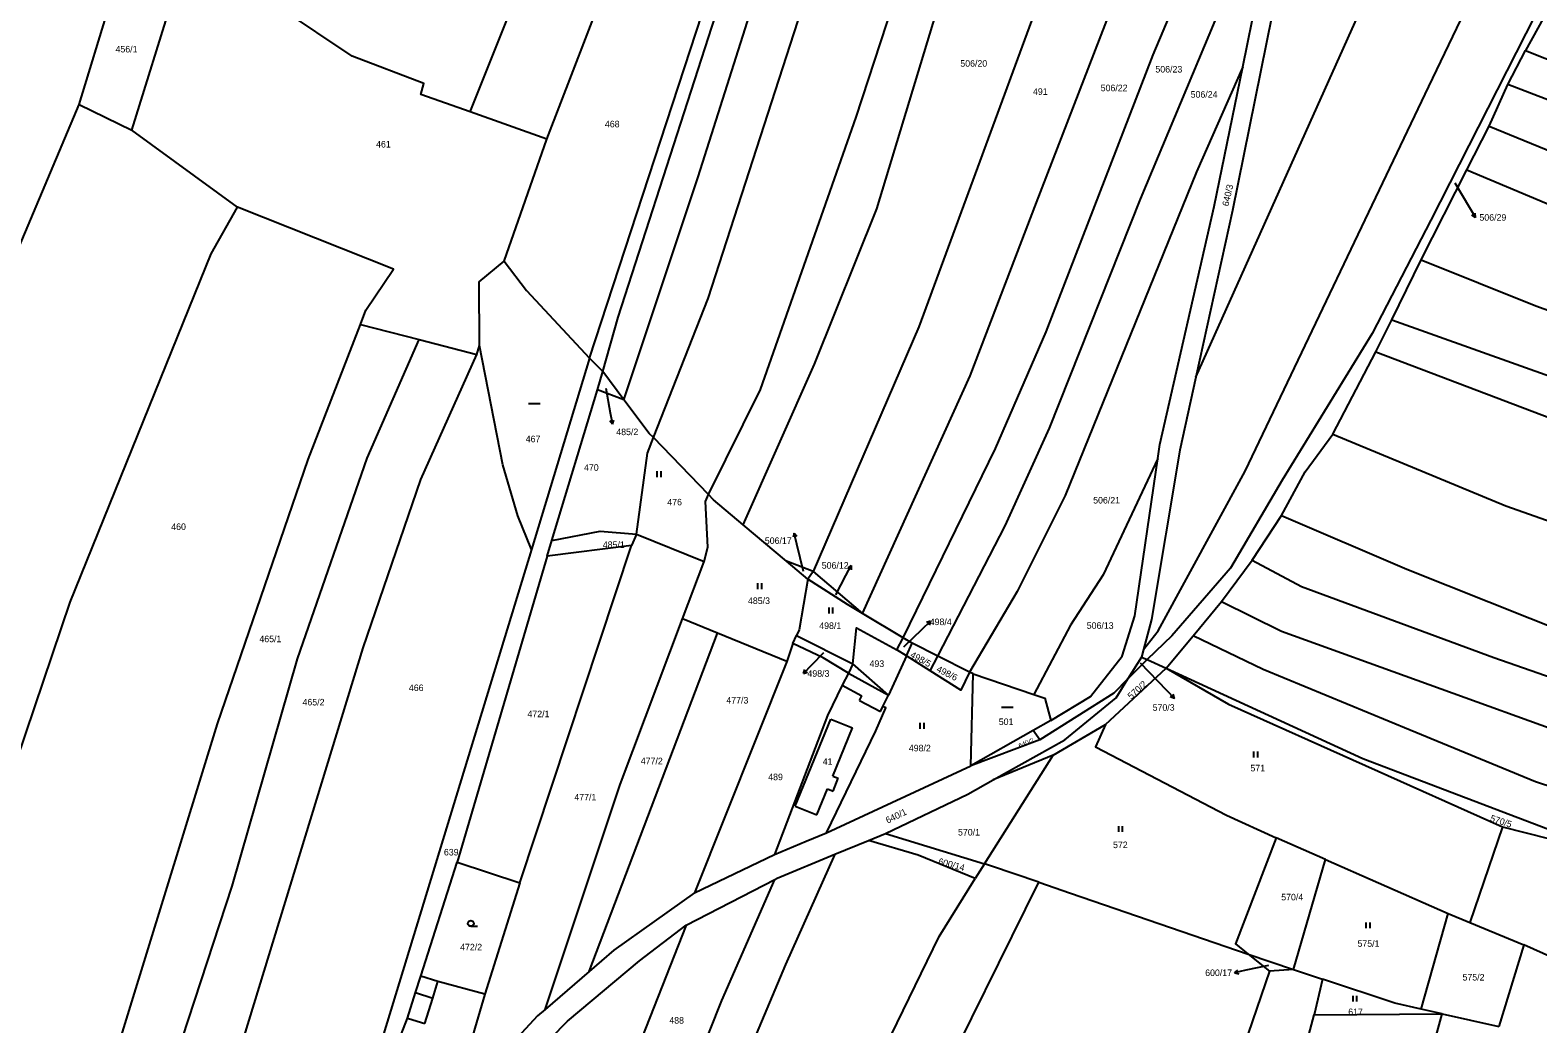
# Model space of a CAD drawing. Extents: x -746176 to -739709, y -1128407 to -1124482.
# Drawn here: x -742864.4 to -742474.2, y -1127139.5 to -1126882.3 of the extents above; entities that cross this region are included whole.
import ezdxf

# ---------------------------------------------------------------- set-up
doc = ezdxf.new("R2010")
doc.units = 0
for name, color, linetype in [('Vrstva 33', 7, 'Continuous'), ('Vrstva 42', 7, 'Continuous'), ('Vrstva 43', 7, 'Continuous'), ('Vrstva 44', 7, 'Continuous'), ('Vrstva 47', 7, 'Continuous')]:
    doc.layers.add(name, color=color, linetype=linetype)

msp = doc.modelspace()

# ---------------------------------------------------------------- linework, layer by layer
at = {"layer": 'Vrstva 33'}
for p, q in [((-742550.57, -1126891.8), (-742539.32, -1126836.74)), ((-742465.86, -1126866.52), (-742477.38, -1126887.58)), ((-742838.1, -1126908.15), (-742827.15, -1126873)), ((-742851.71, -1126901.51), (-742843.85, -1126875.84)), ((-742481.95, -1126896.36), (-742477.38, -1126887.58)), ((-742486.79, -1126907.12), (-742481.95, -1126896.36)), ((-742851.71, -1126901.51), (-742838.1, -1126908.15)), ((-742730.7, -1126910.48), (-742750.49, -1126903.46)), ((-742492.57, -1126918.49), (-742486.79, -1126907.12)), ((-742810.76, -1126928.12), (-742838.1, -1126908.15)), ((-742741.76, -1126942.06), (-742730.7, -1126910.48)), ((-742504.35, -1126941.71), (-742492.57, -1126918.49)), ((-742512.02, -1126957.27), (-742504.35, -1126941.71)), ((-742778.92, -1126958.45), (-742763.72, -1126962.33)), ((-742516.09, -1126965.6), (-742512.02, -1126957.27)), ((-742763.72, -1126962.33), (-742748.81, -1126966.24)), ((-742748.81, -1126966.24), (-742748.07, -1126963.89)), ((-742527.24, -1126986.86), (-742516.09, -1126965.6)), ((-742719.6, -1126967.23), (-742734.68, -1127016.73)), ((-742716.17, -1126970.68), (-742719.6, -1126967.23)), ((-742717.6, -1126975.4), (-742716.17, -1126970.68)), ((-742710.71, -1126977.95), (-742716.17, -1126970.68)), ((-742729.41, -1127014.42), (-742717.6, -1126975.4)), ((-742710.71, -1126977.95), (-742717.6, -1126975.4)), ((-742688.81, -1127002.53), (-742703.1, -1126987.76)), ((-742548.14, -1127019.47), (-742540.51, -1127007.89)), ((-742707.46, -1127012.77), (-742708.78, -1127015.67)), ((-742707.46, -1127012.77), (-742689.92, -1127019.87)), ((-742668.63, -1127019.74), (-742679.87, -1127010.3)), ((-742734.68, -1127016.73), (-742781.25, -1127169.22)), ((-742737.64, -1127102.99), (-742708.78, -1127015.67)), ((-742730.63, -1127018.43), (-742729.41, -1127014.42)), ((-742708.78, -1127015.67), (-742730.63, -1127018.43)), ((-742730.63, -1127018.43), (-742753.9, -1127097.67)), ((-742695.58, -1127034.67), (-742689.92, -1127019.87)), ((-742663.1, -1127024.39), (-742668.63, -1127019.74)), ((-742661.75, -1127022.4), (-742668.63, -1127019.74)), ((-742556.03, -1127030.18), (-742548.14, -1127019.47)), ((-742661.75, -1127022.4), (-742663.1, -1127024.39)), ((-742661.75, -1127022.4), (-742648.95, -1127033.28)), ((-742563.37, -1127039.11), (-742556.03, -1127030.18)), ((-742686.48, -1127038.39), (-742695.58, -1127034.67)), ((-742638.43, -1127039.61), (-742648.95, -1127033.28)), ((-742719.74, -1127125.92), (-742686.48, -1127038.39)), ((-742668.53, -1127045.71), (-742686.48, -1127038.39)), ((-742666.98, -1127041.09), (-742666.02, -1127039.02)), ((-742666.02, -1127039.02), (-742651.5, -1127046.32)), ((-742640.1, -1127042.71), (-742638.43, -1127039.61)), ((-742636.14, -1127040.99), (-742638.43, -1127039.61)), ((-742570.42, -1127047.48), (-742563.37, -1127039.11)), ((-742666.98, -1127041.09), (-742668.53, -1127045.71)), ((-742637.62, -1127044.26), (-742642.23, -1127054.43)), ((-742637.62, -1127044.26), (-742640.1, -1127042.71)), ((-742637.62, -1127044.26), (-742636.14, -1127040.99)), ((-742631.47, -1127048.12), (-742637.62, -1127044.26)), ((-742629.44, -1127044.36), (-742636.14, -1127040.99)), ((-742631.47, -1127048.12), (-742629.44, -1127044.36)), ((-742621.26, -1127048.47), (-742629.44, -1127044.36)), ((-742576.74, -1127044.58), (-742580.29, -1127050.24)), ((-742576.22, -1127042.62), (-742576.74, -1127044.58)), ((-742576.74, -1127044.58), (-742575.31, -1127045.24)), ((-742668.53, -1127045.71), (-742692.49, -1127105.57)), ((-742651.5, -1127046.32), (-742652.6, -1127048.7)), ((-742642.23, -1127054.43), (-742651.5, -1127046.32)), ((-742620.33, -1127048.94), (-742621.26, -1127048.47)), ((-742586.05, -1127061.99), (-742570.42, -1127047.48)), ((-742575.31, -1127045.24), (-742580.29, -1127050.24)), ((-742575.31, -1127045.24), (-742570.42, -1127047.48)), ((-742620.96, -1127072.73), (-742620.33, -1127048.94)), ((-742620.33, -1127048.94), (-742604.64, -1127054.26)), ((-742604.82, -1127063.6), (-742620.96, -1127072.73)), ((-742600.22, -1127061), (-742604.82, -1127063.6)), ((-742603.07, -1127066.02), (-742604.82, -1127063.6)), ((-742599.65, -1127069.95), (-742586.05, -1127061.99)), ((-742603.07, -1127066.02), (-742620.96, -1127072.73)), ((-742617.44, -1127098.12), (-742599.65, -1127069.95)), ((-742599.65, -1127069.95), (-742615.18, -1127076.38)), ((-742658.33, -1127090.03), (-742620.96, -1127072.73)), ((-742647.45, -1127092.03), (-742643.05, -1127090.21)), ((-742643.05, -1127090.21), (-742617.44, -1127098.12)), ((-742529.16, -1127097), (-742541.89, -1127091.38)), ((-742483.35, -1127088.47), (-742491.78, -1127113.29)), ((-742483.35, -1127088.47), (-742452.64, -1127096.27)), ((-742656.1, -1127095.61), (-742647.45, -1127092.03)), ((-742763.33, -1127127.12), (-742753.9, -1127097.67)), ((-742753.9, -1127097.67), (-742737.64, -1127102.99)), ((-742692.49, -1127105.57), (-742671.78, -1127095.63)), ((-742617.44, -1127098.12), (-742619.79, -1127101.89)), ((-742537.43, -1127125.45), (-742529.16, -1127097)), ((-742737.64, -1127102.99), (-742746.73, -1127131.84)), ((-742694.65, -1127113.94), (-742671.65, -1127102.1)), ((-742504.39, -1127135.7), (-742497.42, -1127110.95)), ((-742497.42, -1127110.95), (-742491.78, -1127113.29)), ((-742694.65, -1127113.94), (-742722.13, -1127184.01)), ((-742491.78, -1127113.29), (-742477.79, -1127119.09)), ((-742549.17, -1127121.43), (-742543.65, -1127125.88)), ((-742549.17, -1127121.43), (-742537.43, -1127125.45)), ((-742477.79, -1127119.09), (-742484.3, -1127140.22)), ((-742444.54, -1127133.92), (-742477.79, -1127119.09)), ((-742719.74, -1127125.92), (-742731.14, -1127135.75)), ((-742537.43, -1127125.45), (-742543.65, -1127125.88)), ((-742537.43, -1127125.45), (-742529.93, -1127127.94)), ((-742529.93, -1127127.94), (-742532.11, -1127137.2)), ((-742532.11, -1127137.2), (-742498.96, -1127136.92)), ((-742498.96, -1127136.92), (-742504.39, -1127135.7)), ((-742498.96, -1127136.92), (-742484.3, -1127140.22))]:
    msp.add_line(p, q, dxfattribs=at)
for points in [[(-742679.87, -1127010.3), (-742661.43, -1126968.75), (-742645.29, -1126928.59), (-742630.66, -1126880.5), (-742621.29, -1126852.62), (-742599.04, -1126792.93), (-742588.76, -1126769.25)], [(-742561.23, -1126767.89), (-742567.77, -1126783.13), (-742587.89, -1126832.72), (-742634.42, -1126959.12), (-742661.75, -1127022.4)], [(-742648.95, -1127033.28), (-742621.1, -1126971.78), (-742603.91, -1126926.94), (-742554.63, -1126799.18), (-742540.06, -1126770.15)], [(-742688.81, -1127002.53), (-742675.39, -1126975.35), (-742650.59, -1126904.79), (-742637.92, -1126865.97), (-742628.71, -1126838.73), (-742613.44, -1126798.13), (-742604.44, -1126772.24)], [(-742703.1, -1126987.76), (-742688.91, -1126951.77), (-742648.33, -1126826.13), (-742639.39, -1126803.22), (-742629.18, -1126778.81)], [(-742710.71, -1126977.95), (-742691.49, -1126920.27), (-742659.71, -1126819.94), (-742646.21, -1126781.41)], [(-742638.43, -1127039.61), (-742614.56, -1126990.57), (-742601.46, -1126960.43), (-742573.73, -1126888.65), (-742536.1, -1126799.53), (-742527.67, -1126779.74)], [(-742719.6, -1126967.23), (-742690.51, -1126878.08), (-742694.48, -1126866.91), (-742676.36, -1126812.17), (-742671.59, -1126785.41)], [(-742716.17, -1126970.68), (-742712.23, -1126956.56), (-742687.03, -1126878.58), (-742688.27, -1126869.14), (-742663.45, -1126784.04)], [(-742562.72, -1126972.14), (-742511.64, -1126858.28), (-742475.66, -1126785.18)], [(-742750.49, -1126903.46), (-742732.76, -1126858.93), (-742706.72, -1126793.58)], [(-742730.7, -1126910.48), (-742713.83, -1126866.81), (-742706.14, -1126831.54), (-742708.37, -1126829.06), (-742696.43, -1126791.7)], [(-742576.22, -1127042.62), (-742572.46, -1127037.81), (-742549.96, -1126996.44), (-742502.42, -1126896.85), (-742478.65, -1126847.35), (-742462.47, -1126810.41), (-742451.42, -1126791.4)], [(-742431.72, -1126796.46), (-742469.95, -1126868.69), (-742501.91, -1126931.51), (-742517.1, -1126960.81), (-742540.36, -1126998.76), (-742553.75, -1127021.53), (-742568.92, -1127039.08), (-742575.31, -1127045.24)], [(-742629.44, -1127044.36), (-742612.06, -1127010.59), (-742600.55, -1126985.29), (-742577.05, -1126926.06), (-742554.59, -1126872.35), (-742539.32, -1126836.74)], [(-742750.49, -1126903.46), (-742763.27, -1126898.97), (-742762.5, -1126896.14), (-742781.04, -1126889), (-742799.57, -1126876.62), (-742824.58, -1126865.74)], [(-742541.56, -1126871.36), (-742553.22, -1126928.98), (-742562.72, -1126972.14)], [(-742477.38, -1126887.58), (-742416.04, -1126911.9), (-742348.05, -1126935.25), (-742114.93, -1127013.93), (-742085.96, -1127023.63)], [(-742550.57, -1126891.8), (-742562.56, -1126918.99), (-742596.53, -1127002.73), (-742608.98, -1127027.64), (-742621.26, -1127048.47)], [(-742572.58, -1126993.14), (-742572.06, -1126989.56), (-742557.96, -1126927.95), (-742550.57, -1126891.8)], [(-742089.28, -1127034.5), (-742293.25, -1126965), (-742398.92, -1126928.26), (-742481.95, -1126896.36)], [(-742935.81, -1127130.03), (-742894, -1127011.08), (-742884.2, -1126984.32), (-742867.91, -1126940.04), (-742851.71, -1126901.51)], [(-742486.79, -1126907.12), (-742444.87, -1126924.33), (-742397.83, -1126942.23), (-742288.59, -1126978.66), (-742195.26, -1127011.61), (-742092.54, -1127045.19)], [(-742492.57, -1126918.49), (-742455.79, -1126933.86), (-742390.03, -1126957.98), (-742252.16, -1127003.9), (-742129.68, -1127044.77), (-742095.98, -1127056.46)], [(-742891, -1127139.53), (-742854.01, -1127030.4), (-742817.51, -1126940.24), (-742810.76, -1126928.12)], [(-742778.92, -1126958.45), (-742777.55, -1126954.82), (-742770.36, -1126944.15), (-742810.76, -1126928.12)], [(-742748.07, -1126963.89), (-742748.16, -1126947.44), (-742741.76, -1126942.06)], [(-742741.76, -1126942.06), (-742735.91, -1126949.7), (-742719.6, -1126967.23)], [(-742504.35, -1126941.71), (-742474.75, -1126953.67), (-742378.88, -1126988.04), (-742204.08, -1127046.96), (-742100.58, -1127080.82), (-742076.73, -1127089.67), (-742044, -1127103.72)], [(-742842.98, -1127149.74), (-742815.95, -1127061.82), (-742792.49, -1126993.43), (-742778.92, -1126958.45)], [(-742512.02, -1126957.27), (-742426.6, -1126987.75), (-742322.02, -1127023.9), (-742152.02, -1127080.85), (-742092.77, -1127100.11), (-742049.6, -1127117.15)], [(-742828.27, -1127153.14), (-742812.1, -1127103.89), (-742795.18, -1127045), (-742777.21, -1126993.06), (-742763.72, -1126962.33)], [(-742813.25, -1127156.61), (-742778.25, -1127042.21), (-742763.25, -1126998.63), (-742748.81, -1126966.24)], [(-742734.68, -1127016.73), (-742738.19, -1127008), (-742742.04, -1126994.82), (-742748.07, -1126963.89)], [(-742516.09, -1126965.6), (-742463.84, -1126985.43), (-742374.91, -1127016.27), (-742226.88, -1127065.31), (-742153.9, -1127090.43), (-742091.98, -1127111.83), (-742053.72, -1127127.51)], [(-742562.72, -1126972.14), (-742566.88, -1126991.03), (-742574.16, -1127034.85), (-742576.22, -1127042.62)], [(-742703.1, -1126987.76), (-742704.16, -1126986.66), (-742710.71, -1126977.95)], [(-742707.46, -1127012.77), (-742704.66, -1126991.83), (-742703.1, -1126987.76)], [(-742540.51, -1127007.89), (-742534.38, -1126996.59), (-742527.24, -1126986.86)], [(-742527.24, -1126986.86), (-742482.52, -1127005.44), (-742410.26, -1127030.86), (-742263.45, -1127080.11), (-742124.08, -1127127.86), (-742062.93, -1127150.64)], [(-742572.58, -1126993.14), (-742586.73, -1127023.3), (-742595.13, -1127036.3), (-742604.64, -1127054.26)], [(-742600.22, -1127061), (-742589.93, -1127054.79), (-742581.78, -1127044.3), (-742578.46, -1127033.87), (-742572.58, -1126993.14)], [(-742689.92, -1127019.87), (-742689.01, -1127016.13), (-742689.59, -1127004.26), (-742688.81, -1127002.53)], [(-742679.87, -1127010.3), (-742687.53, -1127003.86), (-742688.81, -1127002.53)], [(-742540.51, -1127007.89), (-742508.14, -1127021.79), (-742465.67, -1127038.76), (-742304.51, -1127093.48), (-742186.57, -1127134.04), (-742101.64, -1127162.49), (-742071.1, -1127173.63)], [(-742729.41, -1127014.42), (-742716.86, -1127011.94), (-742707.46, -1127012.77)], [(-742548.14, -1127019.47), (-742535.36, -1127026.31), (-742485.61, -1127044.66), (-742396.17, -1127075.85), (-742237.29, -1127129.3), (-742102.44, -1127175.98), (-742075.64, -1127186.64)], [(-742663.1, -1127024.39), (-742665.33, -1127037.52), (-742666.02, -1127039.02)], [(-742648.95, -1127033.28), (-742652.83, -1127030.94), (-742663.1, -1127024.39)], [(-742556.03, -1127030.18), (-742540.54, -1127037.88), (-742464.14, -1127065.48), (-742257.87, -1127136.04), (-742181.95, -1127162.82), (-742111.16, -1127186.39), (-742079.42, -1127198.6)], [(-742731.14, -1127135.75), (-742711.74, -1127077.56), (-742695.58, -1127034.67)], [(-742651.5, -1127046.32), (-742650.49, -1127037.02), (-742640.1, -1127042.71)], [(-742081.6, -1127209.14), (-742129.12, -1127193.01), (-742202.75, -1127169.34), (-742345.7, -1127119.16), (-742474.83, -1127076.87), (-742507.28, -1127063.47), (-742545.28, -1127047.75), (-742563.37, -1127039.11)], [(-742652.6, -1127048.7), (-742659.18, -1127044.79), (-742666.98, -1127041.09)], [(-742621.26, -1127048.47), (-742623.51, -1127053.12), (-742631.47, -1127048.12)], [(-742570.42, -1127047.48), (-742519.53, -1127070.81), (-742452.64, -1127096.27)], [(-742570.42, -1127047.48), (-742554.29, -1127056.77), (-742483.35, -1127088.47)], [(-742652.6, -1127048.7), (-742654.28, -1127051.82), (-742658.01, -1127059.67), (-742671.78, -1127095.63)], [(-742615.18, -1127076.38), (-742596.61, -1127065.97), (-742583.33, -1127055.08), (-742580.29, -1127050.24)], [(-742580.29, -1127050.24), (-742583.91, -1127053.87), (-742603.07, -1127066.02)], [(-742658.33, -1127090.03), (-742645.55, -1127063.63), (-742642.98, -1127057.75), (-742643.7, -1127057.4), (-742642.23, -1127054.43)], [(-742604.64, -1127054.26), (-742601.82, -1127055.21), (-742600.22, -1127061)], [(-742586.05, -1127061.99), (-742588.7, -1127067.82), (-742554.78, -1127085.5), (-742541.89, -1127091.38)], [(-742643.05, -1127090.21), (-742621.7, -1127080.04), (-742615.18, -1127076.38)], [(-742671.78, -1127095.63), (-742663.55, -1127092.23), (-742658.33, -1127090.03)], [(-742541.89, -1127091.38), (-742552.48, -1127118.77), (-742549.17, -1127121.43)], [(-742619.79, -1127101.89), (-742634.59, -1127095.86), (-742647.45, -1127092.03)], [(-742656.1, -1127095.61), (-742668.92, -1127124.1), (-742695.82, -1127188.09)], [(-742671.65, -1127102.1), (-742671.07, -1127101.8), (-742656.1, -1127095.61)], [(-742603.37, -1127102.87), (-742615.85, -1127098.61), (-742617.44, -1127098.12)], [(-742529.16, -1127097), (-742515.45, -1127102.99), (-742497.42, -1127110.95)], [(-742706.71, -1127187.05), (-742685.41, -1127133.42), (-742671.65, -1127102.1)], [(-742662.31, -1127190.95), (-742647.78, -1127155.16), (-742629.16, -1127116.92), (-742619.79, -1127101.89)], [(-742644.1, -1127192.22), (-742631.06, -1127158.9), (-742603.37, -1127102.87)], [(-742603.37, -1127102.87), (-742595.15, -1127105.68), (-742549.17, -1127121.43)], [(-742692.49, -1127105.57), (-742713.34, -1127120.39), (-742719.74, -1127125.92)], [(-742738.13, -1127151.87), (-742725.34, -1127138.85), (-742706.66, -1127123.2), (-742694.65, -1127113.94)], [(-742543.65, -1127125.88), (-742554.78, -1127158.4), (-742562.37, -1127191.45), (-742566.48, -1127203.04)], [(-742773.17, -1127157.23), (-742769.01, -1127143.81), (-742766.77, -1127137.99), (-742764.69, -1127131.41), (-742763.33, -1127127.12)], [(-742746.73, -1127131.84), (-742758.85, -1127128.54), (-742763.33, -1127127.12)], [(-742504.39, -1127135.7), (-742511.23, -1127134.16), (-742529.93, -1127127.94)], [(-742746.73, -1127131.84), (-742748.92, -1127139.17), (-742751.52, -1127148.31), (-742756.51, -1127164.2)], [(-742731.14, -1127135.75), (-742733.12, -1127137.46), (-742746.45, -1127151.91), (-742756.51, -1127164.2)], [(-742553.15, -1127238.87), (-742547.82, -1127218.47), (-742536.99, -1127155.61), (-742532.11, -1127137.2)], [(-742523.75, -1127248.38), (-742518.59, -1127225.94), (-742507.29, -1127167.65), (-742498.96, -1127136.92)]]:
    msp.add_lwpolyline(points, dxfattribs=at)
at = {"layer": 'Vrstva 43'}
for p, q in [((-742495.71, -1126921.8), (-742491.86, -1126928.21)), ((-742491.86, -1126928.21), (-742490.31, -1126930.78)), ((-742490.31, -1126930.78), (-742491.26, -1126930.18)), ((-742490.31, -1126930.78), (-742490.4, -1126929.67)), ((-742715.45, -1126974.96), (-742714.25, -1126981.35)), ((-742714.25, -1126981.35), (-742713.68, -1126984.3)), ((-742713.68, -1126984.3), (-742714.36, -1126983.41)), ((-742713.68, -1126984.3), (-742713.38, -1126983.22)), ((-742666.67, -1127012.46), (-742666.91, -1127013.55)), ((-742665.94, -1127015.37), (-742666.67, -1127012.46)), ((-742666.67, -1127012.46), (-742665.94, -1127013.31)), ((-742664.21, -1127022.41), (-742665.94, -1127015.37)), ((-742653.31, -1127023.49), (-742651.9, -1127020.84)), ((-742651.9, -1127020.84), (-742652.81, -1127021.49)), ((-742651.9, -1127020.84), (-742651.93, -1127021.96)), ((-742655.92, -1127028.43), (-742653.31, -1127023.49)), ((-742633.5, -1127037.38), (-742631.34, -1127035.29)), ((-742631.34, -1127035.29), (-742632.41, -1127035.63)), ((-742631.34, -1127035.29), (-742631.71, -1127036.35)), ((-742638.3, -1127041.94), (-742633.5, -1127037.38)), ((-742659.09, -1127043.5), (-742662.15, -1127046.66)), ((-742662.15, -1127046.66), (-742664.23, -1127048.82)), ((-742664.23, -1127048.82), (-742663.9, -1127047.75)), ((-742664.23, -1127048.82), (-742663.18, -1127048.45)), ((-742577.15, -1127046.1), (-742570.34, -1127053.11)), ((-742570.34, -1127053.11), (-742568.26, -1127055.27)), ((-742568.26, -1127055.27), (-742569.31, -1127054.9)), ((-742568.26, -1127055.27), (-742568.59, -1127054.2)), ((-742552.69, -1127126.26), (-742551.81, -1127125.57)), ((-742549.75, -1127125.64), (-742552.69, -1127126.26)), ((-742552.69, -1127126.26), (-742551.6, -1127126.55)), ((-742543.87, -1127124.36), (-742549.75, -1127125.64))]:
    msp.add_line(p, q, dxfattribs=at)
at = {"layer": 'Vrstva 44'}
for p, q in [((-742735.42, -1126978.93), (-742732.42, -1126978.93)), ((-742702.11, -1126997.97), (-742702.11, -1126996.47)), ((-742701.11, -1126997.97), (-742701.11, -1126996.47)), ((-742676.05, -1127026.97), (-742676.05, -1127025.47)), ((-742675.05, -1127026.97), (-742675.05, -1127025.47)), ((-742657.63, -1127033.26), (-742657.63, -1127031.76)), ((-742656.63, -1127033.26), (-742656.63, -1127031.76)), ((-742612.97, -1127057.56), (-742609.97, -1127057.56)), ((-742634.04, -1127063.11), (-742634.04, -1127061.61)), ((-742633.04, -1127063.11), (-742633.04, -1127061.61)), ((-742547.69, -1127070.53), (-742547.69, -1127069.03)), ((-742546.69, -1127070.53), (-742546.69, -1127069.03)), ((-742582.67, -1127089.81), (-742582.67, -1127088.31)), ((-742581.67, -1127089.81), (-742581.67, -1127088.31)), ((-742750.34, -1127114.24), (-742748.59, -1127114.24)), ((-742518.62, -1127114.73), (-742518.62, -1127113.23)), ((-742517.62, -1127114.73), (-742517.62, -1127113.23)), ((-742522.03, -1127133.76), (-742522.03, -1127132.26)), ((-742521.03, -1127133.76), (-742521.03, -1127132.26))]:
    msp.add_line(p, q, dxfattribs=at)
msp.add_circle((-742750.34, -1127113.49), 0.75, dxfattribs=at)
at = {"layer": 'Vrstva 47'}
for p, q in [((-742654.28, -1127051.82), (-742649.19, -1127054.59)), ((-742652.6, -1127048.7), (-742642.23, -1127054.43)), ((-742649.73, -1127055.83), (-742649.19, -1127054.59)), ((-742649.73, -1127055.83), (-742644.34, -1127058.7)), ((-742644.34, -1127058.7), (-742643.7, -1127057.4)), ((-742666.37, -1127083.14), (-742657.21, -1127060.61)), ((-742657.21, -1127060.61), (-742651.6, -1127062.89)), ((-742656.67, -1127075.36), (-742651.6, -1127062.89)), ((-742656.67, -1127075.36), (-742655.24, -1127075.94)), ((-742660.76, -1127085.42), (-742658.03, -1127078.7)), ((-742658.03, -1127078.7), (-742656.59, -1127079.28)), ((-742656.59, -1127079.28), (-742655.24, -1127075.94)), ((-742666.37, -1127083.14), (-742660.76, -1127085.42)), ((-742760.21, -1127132.83), (-742758.85, -1127128.54)), ((-742764.69, -1127131.41), (-742760.21, -1127132.83)), ((-742762.29, -1127139.41), (-742760.21, -1127132.83)), ((-742766.77, -1127137.99), (-742765.39, -1127138.43)), ((-742765.39, -1127138.43), (-742762.29, -1127139.41))]:
    msp.add_line(p, q, dxfattribs=at)

# ---------------------------------------------------------------- texts
at = {"layer": 'Vrstva 42'}
for s, p in [('456/1', (-742842.3, -1126888.07)), ('506/20', (-742623.66, -1126891.77)), ('506/23', (-742573.17, -1126893.27)), ('506/22', (-742587.33, -1126898.11)), ('491', (-742604.85, -1126899.05)), ('506/24', (-742564.05, -1126899.79)), ('468', (-742715.64, -1126907.46)), ('461', (-742774.87, -1126912.68)), ('506/29', (-742489.31, -1126931.63)), ('485/2', (-742712.7, -1126987.13)), ('467', (-742736.14, -1126988.97)), ('470', (-742721.05, -1126996.36)), ('476', (-742699.5, -1127005.32)), ('506/21', (-742589.28, -1127004.82)), ('460', (-742827.88, -1127011.68)), ('485/1', (-742716.19, -1127016.34)), ('506/17', (-742674.26, -1127015.29)), ('506/12', (-742659.52, -1127021.69)), ('485/3', (-742678.62, -1127030.84)), ('498/1', (-742660.17, -1127037.3)), ('498/4', (-742631.58, -1127036.3)), ('506/13', (-742590.94, -1127037.26)), ('465/1', (-742805.07, -1127040.72)), ('498/3', (-742663.23, -1127049.67)), ('493', (-742647.16, -1127047.13)), ('466', (-742766.38, -1127053.37)), ('465/2', (-742793.91, -1127057.09)), ('477/3', (-742684.22, -1127056.6)), ('472/1', (-742735.69, -1127060.13)), ('570/3', (-742573.89, -1127058.47)), ('501', (-742613.71, -1127062.16)), ('498/2', (-742636.99, -1127068.98)), ('477/2', (-742706.36, -1127072.31)), ('41', (-742659.27, -1127072.46)), ('489', (-742673.38, -1127076.44)), ('571', (-742548.58, -1127074.15)), ('477/1', (-742723.56, -1127081.69)), ('570/1', (-742624.26, -1127090.76)), ('639', (-742757.31, -1127095.92)), ('572', (-742584.14, -1127094.02)), ('570/4', (-742540.61, -1127107.55)), ('472/2', (-742753.12, -1127120.49)), ('575/1', (-742520.87, -1127119.56)), ('600/17', (-742560.29, -1127127.13)), ('575/2', (-742493.69, -1127128.29)), ('488', (-742698.98, -1127139.45)), ('617', (-742523.26, -1127137.24))]:
    msp.add_text(s, height=1.7, dxfattribs=at).set_placement(p)
for s, height, rotation, p in [('640/3', 1.7, 77, (-742554.27, -1126928)), ('498/5', 1.7, 331, (-742636.79, -1127044.49)), ('498/6', 1.7, 333, (-742629.99, -1127048.22)), ('570/2', 1.7, 42, (-742579.45, -1127055.61)), ('640/2', 1.19, 22, (-742608.31, -1127068.09)), ('640/1', 1.7, 26, (-742642.46, -1127087.71)), ('570/5', 1.7, 342, (-742486.68, -1127087)), ('600/14', 1.7, 345, (-742629.52, -1127098.19))]:
    msp.add_text(s, height=height, rotation=rotation, dxfattribs=at).set_placement(p)

doc.saveas('drawing.dxf')
